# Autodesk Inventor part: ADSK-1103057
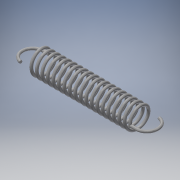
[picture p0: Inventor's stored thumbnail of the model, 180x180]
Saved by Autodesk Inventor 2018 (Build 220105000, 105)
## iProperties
Shininess: 20.0
Length Units: 11269
Angle Units: 11279
Time Units: 11290
Mass Units: 11283
Length Display Precision: 3
Angle Display Precision: 2
Created: 2001-06
Part Number: ADSK-1103057
Material: Steel, Mild
Document SubType Name: Modeling
Description: UHAN #3.873-ESX
Mass: 0.263888 g
Surface Area: 2.99213 cm^2
Volume: 0.0335735 cm^3
Density: 7.86 g/cm^3
Appearance: Steel
Density: 7.86
Volumn: 3.5806394370622003
Area: 32.24046301072255
PropertySet Name: Model Information
Control State: 0
Master: False
Checked Out: False
msp_n: 18.000 ul
+MSCProtocol1+ProtocolID: P00060125011928546
+MSCProtocol2+Protocol: P00060125011928546<@PID>[Version]<@EL>Version=2.2<@EL>[Material]<@EL>MatID=<@EL>Material=User<@EL>Density=7850<@EL>[CalcData]<@EL>Scn1= 0<@EL>Scn2= 0<@EL>Scn3= 
Author: Autodesk, Inc.
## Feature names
1. Coil1
2. Revolution1
3. Sweep1
4. Sweep2
5. Revolution2
6. Sweep4
7. Sweep5
## Parameters: d0 = 1.7115 mm, d1 = 0.45 mm, prf_d = 0.45 mm, prf_D1 = 3.873 mm, d2 = 0.88844 mm, d4 = 185 mm, d5 = 0, d6 = 90 deg, d7 = 90 deg, d8 = 0, d9 = 0, prf_wl = 21 mm, prf_o = 2.504 mm, msp_L = 15.992 mm, d10 = -0.225 mm, d11 = 0.225 mm, d12 = 1.7115 mm, d14 = 90 deg, d15 = 1.0175 mm, d16 = 0, d17 = 0.45 mm, d18 = 0, d21 = 170 deg, d22 = 0.45 mm, d23 = 0, d24 = 0.225 mm, d25 = 90 deg, d29 = 16.21122 mm, d30 = 0, d31 = 1.7115 mm, d39 = 0.45 mm, d40 = 1.0175 mm, d41 = 0, d42 = 0, d43 = 170 deg, d44 = 0.45 mm, d45 = 0, d46 = 0, d47 = 0, d48 = 0, d49 = 0
